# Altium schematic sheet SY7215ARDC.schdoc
size 127 x 101 mm
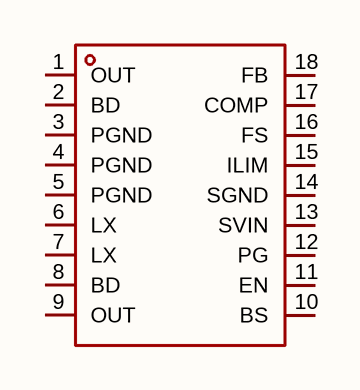
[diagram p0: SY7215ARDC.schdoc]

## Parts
U?  sy7215ardc  [QFN-18_L4.0-W4.0_SY7215ARDC]  (value not drawn)

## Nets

Not connected (* = marked no-connect by the designer): U? 1(OUT) 2(BD) 3(PGND) 4(PGND) 5(PGND) 6(LX) 7(LX) 8(BD) 9(OUT) 10(BS) 11(EN) 12(PG) 13(SVIN) 14(SGND) 15(ILIM) 16(FS) 17(COMP) 18(FB)

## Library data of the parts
U? = sy7215ardc: 功能类型:升压型;工作电压:3V~16V;输出电压:-;输出电流:-;输出类型:可调;; Manufacturer: Silergy(矽力杰); AddInBom: yes; ModelId: 7e44abbd101e444bb2ad56d870fef471; ModelTransform: 158.267,158.267,0,0,0,0,-5.508,-2.127,0; Function: 升压型; Voltage - Supply: 3V~16V; Frequency - Switching: 250kHz~1MHz；345kHz; Synchronous Rectifier: 是; Number of Outputs: 1; Topology: 升压式; Quiescent Current: 230uA; Switch tube (built-in/external): 内置; Output Type: 可调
